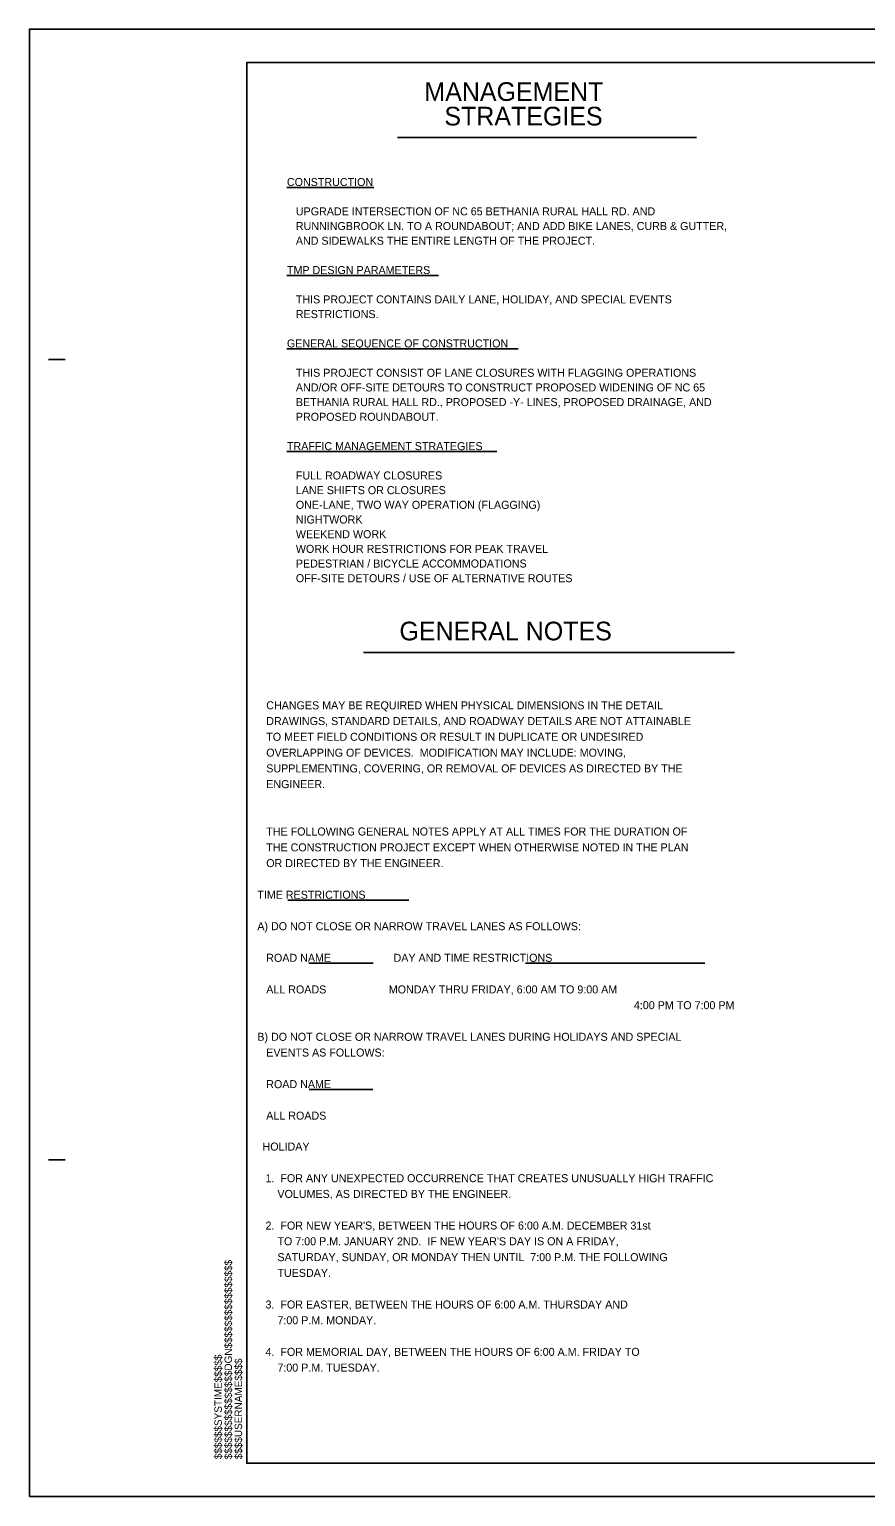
# Model space of a CAD drawing. Extents: x 762655 to 770567, y 650864 to 655190.
# Drawn here: x 762655 to 763282, y 652779 to 653879 of the extents above; entities that cross this region are included whole.
import ezdxf

# ---------------------------------------------------------------- set-up
doc = ezdxf.new("R2010")
doc.units = 0
for name, color, linetype in [('Default', 7, 'Continuous'), ('DEV BORDER CELL', 7, 'Continuous'), ('DEV TRANSPORTATION OPERATIONS PLAN SHEET', 7, 'Continuous'), ('Sheet Plot Border Outside CELL', 7, 'Continuous')]:
    doc.layers.add(name, color=color, linetype=linetype)

msp = doc.modelspace()

# ---------------------------------------------------------------- linework, layer by layer
at = {"layer": 'Default'}
for p, q in [((762847.9, 653760.2), (762913, 653760.2)), ((762847.9, 653694.2), (762961.6, 653694.2)), ((762847.9, 653639.2), (763021.1, 653639.2)), ((762847.9, 653562.2), (763005.2, 653562.2)), ((762848.5, 653226), (762939.2, 653226)), ((762864.3, 653178.6), (762912.5, 653178.6)), ((763026.7, 653178.6), (763161.1, 653178.6)), ((762864.5, 653084), (762912.4, 653084))]:
    msp.add_line(p, q, dxfattribs=at)
at = {"layer": 'DEV BORDER CELL'}
for p, q in [((762930.8, 653797.6), (763154.8, 653797.6)), ((762905.4, 653411.6), (763183.3, 653411.6))]:
    msp.add_line(p, q, dxfattribs=at)
at = {"layer": 'DEV TRANSPORTATION OPERATIONS PLAN SHEET'}
for p, q in [((762818.8, 653853.8), (762818.8, 653853.8)), ((762669.3, 653631.3), (762681.8, 653631.3)), ((762669.3, 653031.3), (762681.8, 653031.3)), ((762817.8, 652803.8), (762817.8, 652803.8))]:
    msp.add_line(p, q, dxfattribs=at)
msp.add_lwpolyline([(764317.9, 653853.8), (762817.8, 653853.8), (762817.8, 652803.8), (764317.9, 652803.8)], close=True, dxfattribs=at)
at = {"layer": 'Sheet Plot Border Outside CELL'}
msp.add_lwpolyline([(762654.9, 652778.8), (764342.9, 652778.8), (764342.9, 653878.8), (762654.9, 653878.8)], close=True, dxfattribs=at)

# ---------------------------------------------------------------- texts
at = {"layer": 'Default'}
for s, p in [('CONSTRUCTION', (762847.9, 653761.3)), ('   UPGRADE INTERSECTION OF NC 65 BETHANIA RURAL HALL RD. AND ', (762847.9, 653739.3)), ('   RUNNINGBROOK LN. TO A ROUNDABOUT; AND ADD BIKE LANES, CURB & GUTTER,', (762847.9, 653728.3)), ('   AND SIDEWALKS THE ENTIRE LENGTH OF THE PROJECT.', (762847.9, 653717.3)), ('TMP DESIGN PARAMETERS', (762847.9, 653695.3)), ('   THIS PROJECT CONTAINS DAILY LANE, HOLIDAY, AND SPECIAL EVENTS ', (762847.9, 653673.3)), ('   RESTRICTIONS.', (762847.9, 653662.3)), ('GENERAL SEQUENCE OF CONSTRUCTION', (762847.9, 653640.3)), ('   THIS PROJECT CONSIST OF LANE CLOSURES WITH FLAGGING OPERATIONS', (762847.9, 653618.3)), ('   AND/OR OFF-SITE DETOURS TO CONSTRUCT PROPOSED WIDENING OF NC 65', (762847.9, 653607.3)), ('   BETHANIA RURAL HALL RD., PROPOSED -Y- LINES, PROPOSED DRAINAGE, AND', (762847.9, 653596.3)), ('   PROPOSED ROUNDABOUT.', (762847.9, 653585.3)), ('TRAFFIC MANAGEMENT STRATEGIES', (762847.9, 653563.3)), ('   FULL ROADWAY CLOSURES', (762847.9, 653541.3)), ('   LANE SHIFTS OR CLOSURES', (762847.9, 653530.3)), ('   ONE-LANE, TWO WAY OPERATION (FLAGGING)', (762847.9, 653519.3)), ('   NIGHTWORK', (762847.9, 653508.3)), ('   WEEKEND WORK', (762847.9, 653497.3)), ('   WORK HOUR RESTRICTIONS FOR PEAK TRAVEL', (762847.9, 653486.3)), ('   PEDESTRIAN / BICYCLE ACCOMMODATIONS', (762847.9, 653475.3)), ('   OFF-SITE DETOURS / USE OF ALTERNATIVE ROUTES', (762847.9, 653464.3)), ('          CHANGES MAY BE REQUIRED WHEN PHYSICAL DIMENSIONS IN THE DETAIL ', (762810.1, 653369)), ('          DRAWINGS, STANDARD DETAILS, AND ROADWAY DETAILS ARE NOT ATTAINABLE ', (762810.1, 653357.2)), ('          TO MEET FIELD CONDITIONS OR RESULT IN DUPLICATE OR UNDESIRED ', (762810.1, 653345.4)), ('          OVERLAPPING OF DEVICES.  MODIFICATION MAY INCLUDE: MOVING, ', (762810.1, 653333.5)), ('          SUPPLEMENTING, COVERING, OR REMOVAL OF DEVICES AS DIRECTED BY THE ', (762810.1, 653321.7)), ('          ENGINEER.  ', (762810.1, 653309.9)), ('          THE FOLLOWING GENERAL NOTES APPLY AT ALL TIMES FOR THE DURATION OF', (762810.1, 653274.4)), ('          THE CONSTRUCTION PROJECT EXCEPT WHEN OTHERWISE NOTED IN THE PLAN', (762810.1, 653262.5)), ('          OR DIRECTED BY THE ENGINEER.', (762810.1, 653250.7)), ('       TIME RESTRICTIONS ', (762810.1, 653227)), ('       A) DO NOT CLOSE OR NARROW TRAVEL LANES AS FOLLOWS:', (762810.1, 653203.4)), ('          ROAD NAME                     DAY AND TIME RESTRICTIONS', (762810.1, 653179.7)), ('          ALL ROADS                     MONDAY THRU FRIDAY, 6:00 AM TO 9:00 AM                 ', (762810.1, 653156)), ('        4:00 PM TO 7:00 PM', (763090.1, 653144.2)), ('       B) DO NOT CLOSE OR NARROW TRAVEL LANES DURING HOLIDAYS AND SPECIAL', (762810.1, 653120.5)), ('          EVENTS AS FOLLOWS:', (762810.1, 653108.7)), ('          ROAD NAME ', (762810.1, 653085)), ('          ALL ROADS ', (762810.1, 653061.4)), ('           HOLIDAY', (762805.1, 653038.2)), ('            1.  FOR ANY UNEXPECTED OCCURRENCE THAT CREATES UNUSUALLY HIGH TRAFFIC ', (762805.1, 653014.5)), ('                VOLUMES, AS DIRECTED BY THE ENGINEER.', (762805.1, 653002.7)), ("            2.  FOR NEW YEAR'S, BETWEEN THE HOURS OF 6:00 A.M. DECEMBER 31st", (762805.1, 652979)), ("                TO 7:00 P.M. JANUARY 2ND.  IF NEW YEAR'S DAY IS ON A FRIDAY,", (762805.1, 652967.2)), ('                SATURDAY, SUNDAY, OR MONDAY THEN UNTIL  7:00 P.M. THE FOLLOWING ', (762805.1, 652955.3)), ('                TUESDAY.  ', (762805.1, 652943.5)), ('            3.  FOR EASTER, BETWEEN THE HOURS OF 6:00 A.M. THURSDAY AND', (762805.1, 652919.8)), ('                7:00 P.M. MONDAY.', (762805.1, 652908)), ('            4.  FOR MEMORIAL DAY, BETWEEN THE HOURS OF 6:00 A.M. FRIDAY TO', (762805.1, 652884.3)), ('                7:00 P.M. TUESDAY.', (762805.1, 652872.5))]:
    msp.add_text(s, height=6, dxfattribs=at).set_placement(p)
at = {"layer": 'DEV TRANSPORTATION OPERATIONS PLAN SHEET'}
for s, p in [('MANAGEMENT ', (762950.9, 653825.1)), ('STRATEGIES', (762965.9, 653806.7)), ('GENERAL NOTES', (762932.2, 653420.7))]:
    msp.add_text(s, height=14, dxfattribs=at).set_placement(p)
for s, p in [('$$$$$$$$$$$$$$$$DGN$$$$$$$$$$$$$$$$', (762806.7, 652806.8)), ('$$$$$$SYSTIME$$$$$', (762799.1, 652806.8)), ('$$$$USERNAME$$$$', (762814.3, 652806.8))]:
    msp.add_text(s, height=5.584, rotation=90, dxfattribs=at).set_placement(p)

doc.saveas('drawing.dxf')
